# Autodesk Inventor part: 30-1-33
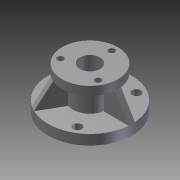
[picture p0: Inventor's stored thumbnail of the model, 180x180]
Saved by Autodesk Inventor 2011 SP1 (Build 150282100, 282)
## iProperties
Created: 2014-02
Part Number: 30-1-33
Document SubType Name: Modeling
Designer: Administrator
Density: 1 g/cm^3
Author: Administrator
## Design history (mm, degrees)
sketch "草图1"
  geometry: C1 r 11 at (0, 0); C2 r 6.5 at (0, 0); 1 further point
  constraints: 2 centre point, 2 coincident
  dimensions: "d0" = 22 diameter of C1; "d1" = 13 diameter of C2
extrude "拉伸1" new body sketch "草图1" distance "d2" = 30; taper "d3" = 0 deg
sketch "草图2"
  geometry: C1 r 11 at (0, 0) reference; C2 r 18 at (0, 0)
  constraints: 1 centre point, 1 coincident
  dimensions: "d4" = 36 diameter of C2
extrude "拉伸2" join sketch "草图2" distance "d5" = 5.5; taper "d6" = 0 deg
node "工作平面1"
sketch "草图3"
  geometry: C1 r 27 at (0, 0); 1 further point
  constraints: 1 centre point, 1 coincident
  dimensions: "d8" = 54 diameter of C1
extrude "拉伸3" join sketch "草图3" distance "d9" = 6.5; taper "d10" = 0 deg
hole "Hole1" diameter "d13" = 13; stored, may be unused: countersink angle "d17" = 90 deg, drill point angle "d19" = 118 deg; dims "d11" = 10, "d12" = 10, "d14" = 6, "d15" = 4, "d16" = 2, "d18" = 8
sketch "草图4"
  geometry: C1 r 27 at (0, 0) reference; 1 further point
  dimensions: "d20" = 22 distance of C1.centre point (-22, 0)
hole "Hole2" sketch "草图4" at (-22, 0) diameter "d21" = 5.5; stored, may be unused: countersink angle "d25" = 90 deg, drill point angle "d27" = 118 deg; dims "d22" = 6, "d23" = 4, "d24" = 2, "d26" = 8
pattern_circular "环形阵列1" dims angle "d29" = 360 deg
sketch "草图5"
  geometry: C1 r 18 at (0, 0) reference; 1 further point
  dimensions: "d31" = 14 distance of point (0, 14) C1.centre
hole "Hole3" sketch "草图5" at (0, 14) diameter "d32" = 4; stored, may be unused: countersink angle "d36" = 90 deg, drill point angle "d38" = 118 deg; dims "d33" = 6, "d34" = 4, "d35" = 2, "d37" = 6
pattern_circular "环形阵列2" dims angle "d40" = 360 deg
sketch "草图6"
  geometry: L1 (18, 24.5)-(-18, 24.5) reference; L2 (-27, 9.5)-(27, 9.5) reference; L3 (-11, 9.5)-(-11, 24.5) reference; L4 (-18, 24.5)-(-27, 9.5); 1 further point
  constraints: 2 end point
extrude "拉伸4" join sketch "草图6" stored distance "d42" = 4; taper "d43" = 0 deg
pattern_circular "环形阵列3" dims angle "d45" = 360 deg
node "实体1"
other parameters: "d7" = -3
